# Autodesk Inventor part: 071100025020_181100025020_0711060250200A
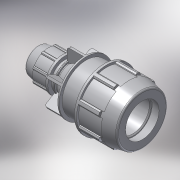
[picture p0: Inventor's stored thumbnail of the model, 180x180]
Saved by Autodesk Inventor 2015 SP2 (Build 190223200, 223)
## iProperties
Created: 2017-02
Part Number: 071100025020_181100025020_0711060250200A
Material: PVC-Piping
Description: PLASSON REDUCING COUPLER 25-20
Document SubType Name: Modeling
Designer: KIM
Mass: 92.6774 g
Surface Area: 199.44 cm^2
Volume: 66.1981 cm^3
Density: 1.4 g/cm^3
Appearance: Smooth - White
Author: KIM
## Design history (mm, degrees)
derived "07110.ipt"
feature "Solid1::07110.ipt"
tag "TaggingFeature1"
body "Solid1"
other parameters: "d2" = 25, "d4" = 9.91667, "d5" = 17, "d7" = 54, "d9" = 17, "d11" = 1.7, "d12" = 43.2, "d13" = 120 deg, "d14" = 37.5, "d15" = 12 deg, "d16" = 48.6, "d18" = 1.25, "d19" = 35 deg, "d20" = 17.5 deg, "d21" = 50.22, "d23" = 0, "d25" = 360 deg, "d27" = 1.08, "d42" = 26.18, "d46" = 0.75, "d51" = 119, "d52" = 17, "d53" = 12 deg, "d54" = 58, "d58" = 22.5, "d59" = 18, "d60" = 43.2, "d61" = 38.4, "d62" = 11.9, "d63" = 19.04, "d64" = 120 deg, "d65" = 48, "d68" = 8.5, "d74" = 44.64, "d75" = 35 deg, "d76" = 17.5 deg, "d78" = 0, "d80" = 360 deg, "d85" = 0.96, "d88" = 0.4, "d93" = 57, "d94" = 37.8, "d97" = 2.21667, "d98" = 3.2, "d99" = 0, "d100" = 2.16, "d102" = 360 deg, "d104" = 2, "d106" = 0, "d107" = 3.2, "d108" = 0, "d109" = 3.2, "d110" = 0, "d_" = 25, "E_" = 54, "H_" = 119, "l_" = 58, "E_1" = 48, "l_1" = 57, "d96" = 6.65
